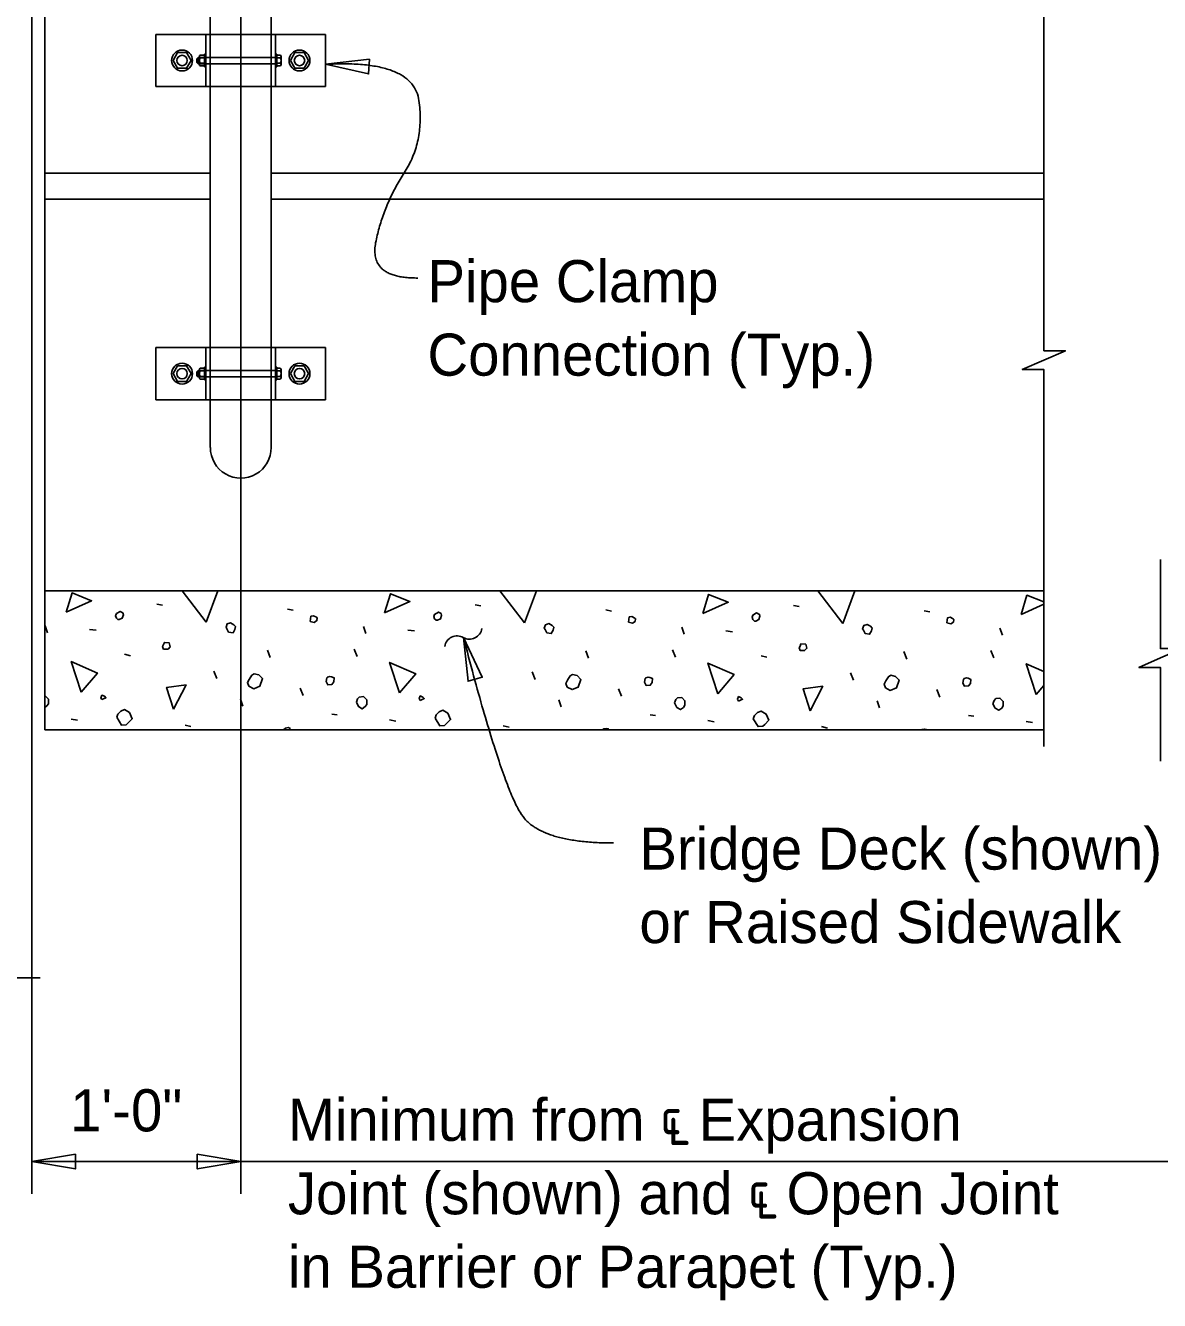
# Model space of a CAD drawing. Extents: x 0 to 72.1, y -15.2 to 30.1.
# Drawn here: x 23.6 to 29.03, y 12.88 to 18.99 of the extents above; entities that cross this region are included whole.
import ezdxf

# ---------------------------------------------------------------- set-up
doc = ezdxf.new("R2010")
doc.units = 0
for name, color, linetype in [('AdhocPoint_dp', 7, 'Continuous'), ('Border', 7, 'Continuous'), ('Patterning', 7, 'Continuous'), ('PlotBorder_dp', 7, 'Continuous'), ('SheetBorder_dp', 7, 'Continuous'), ('SheetLines_dp', 7, 'Continuous'), ('TextMisc', 7, 'Continuous')]:
    doc.layers.add(name, color=color, linetype=linetype)

msp = doc.modelspace()

# ---------------------------------------------------------------- linework, layer by layer
at = {"layer": 'AdhocPoint_dp'}
for p, q in [((23.6923, 19.2783), (23.6923, 15.6116)), ((23.6923, 18.2783), (24.4852, 18.2783)), ((24.7769, 18.2783), (28.4755, 18.2783)), ((24.7769, 18.2783), (26.018, 18.2783)), ((23.6924, 18.1533), (24.4853, 18.1533)), ((24.7769, 18.1533), (28.4756, 18.1533)), ((23.6923, 16.2783), (28.4755, 16.2783)), ((23.6923, 15.6116), (28.4755, 15.6116))]:
    msp.add_line(p, q, dxfattribs=at)
at = {"layer": 'Border'}
for p, q in [((24.4852, 18.9432), (24.4852, 18.6932)), ((24.7769, 18.9432), (24.7769, 18.6932)), ((24.7978, 18.8328), (24.4329, 18.8328)), ((24.4329, 18.8029), (24.7978, 18.8029)), ((24.4852, 17.4432), (24.4852, 17.1932)), ((24.7769, 17.4432), (24.7769, 17.1932)), ((24.7978, 17.3328), (24.4329, 17.3328)), ((24.4329, 17.3029), (24.7978, 17.3029))]:
    msp.add_line(p, q, dxfattribs=at)
at = {"layer": 'Patterning'}
for p, q in [((24.4235, 18.8113), (24.4235, 18.8234)), ((24.4292, 18.8113), (24.4292, 18.8234)), ((24.4235, 17.3113), (24.4235, 17.3234)), ((24.4292, 17.3113), (24.4292, 17.3234)), ((24.2297, 16.2147), (24.2563, 16.2094)), ((24.8555, 16.1899), (24.882, 16.1846)), ((25.7536, 16.2111), (25.7801, 16.2058)), ((26.3793, 16.1864), (26.4059, 16.1811)), ((27.2774, 16.2076), (27.3039, 16.2023)), ((27.9032, 16.1829), (27.9297, 16.1775)), ((23.7065, 16.0768), (23.6941, 16.1104)), ((23.9062, 16.0927), (23.9381, 16.0892)), ((25.2303, 16.0733), (25.2179, 16.1068)), ((25.43, 16.0892), (25.4619, 16.0856)), ((26.7541, 16.0697), (26.7417, 16.1033)), ((26.9539, 16.0856), (26.9857, 16.0821)), ((28.2779, 16.0662), (28.2655, 16.0998)), ((24.0742, 15.9743), (24.1025, 15.9672)), ((24.7724, 15.9583), (24.7583, 15.9937)), ((25.1879, 15.9636), (25.1737, 15.999)), ((26.2963, 15.9548), (26.2821, 15.9902)), ((26.7117, 15.9601), (26.6975, 15.9955)), ((27.1218, 15.9672), (27.1501, 15.9601)), ((27.8201, 15.9513), (27.8059, 15.9866)), ((28.2355, 15.9566), (28.2214, 15.9919)), ((24.5161, 15.8576), (24.502, 15.8929)), ((26.0399, 15.854), (26.0258, 15.8894)), ((27.5637, 15.8505), (27.5496, 15.8859)), ((24.6416, 15.725), (24.6293, 15.7586)), ((24.9298, 15.7763), (24.9156, 15.8116)), ((26.4536, 15.7727), (26.4394, 15.8081)), ((27.9774, 15.7692), (27.9633, 15.8046)), ((26.1654, 15.7215), (26.1531, 15.7551)), ((27.6893, 15.7179), (27.6769, 15.7515)), ((23.8196, 15.6631), (23.8497, 15.6578)), ((24.3641, 15.6348), (24.3924, 15.6278)), ((25.0677, 15.6879), (25.0924, 15.6843)), ((25.3434, 15.6596), (25.3735, 15.6543)), ((26.5915, 15.6843), (26.6162, 15.6808)), ((26.8672, 15.6561), (26.8973, 15.6508)), ((28.1153, 15.6808), (28.14, 15.6773)), ((28.3911, 15.6525), (28.4211, 15.6472)), ((25.8879, 15.6313), (25.9162, 15.6242)), ((27.4117, 15.6278), (27.44, 15.6207))]:
    msp.add_line(p, q, dxfattribs=at)
for points in [[(23.7949, 16.1758), (23.8231, 16.2677), (23.9168, 16.2306), (23.7949, 16.1758)], [(24.4648, 16.1281), (24.3507, 16.2783)], [(24.521, 16.2783), (24.4648, 16.1281)], [(25.3187, 16.1722), (25.347, 16.2642), (25.4407, 16.227), (25.3187, 16.1722)], [(25.9887, 16.1245), (25.8718, 16.2783)], [(26.0461, 16.2783), (25.9887, 16.1245)], [(26.8425, 16.1687), (26.8708, 16.2606), (26.9645, 16.2235), (26.8425, 16.1687)], [(27.5125, 16.121), (27.3929, 16.2783)], [(27.5713, 16.2783), (27.5125, 16.121)], [(28.3663, 16.1652), (28.3946, 16.2571), (28.4755, 16.225)], [(28.4755, 16.2143), (28.3663, 16.1652)], [(24.0424, 16.1404), (24.0494, 16.1404), (24.0636, 16.1475), (24.0689, 16.1634), (24.0671, 16.1722), (24.053, 16.1793), (24.0353, 16.1687), (24.0317, 16.1581), (24.0353, 16.1475), (24.0424, 16.1404)], [(24.5638, 16.0962), (24.5727, 16.0803), (24.5939, 16.0768), (24.6027, 16.0927), (24.6063, 16.1068), (24.5974, 16.1157), (24.5815, 16.1245), (24.5656, 16.1192), (24.5603, 16.1033), (24.5638, 16.0962)], [(24.9634, 16.1316), (24.9828, 16.1263), (24.9952, 16.1351), (24.9969, 16.1475), (24.9934, 16.151), (24.9793, 16.1581), (24.9669, 16.1563), (24.9651, 16.144), (24.9634, 16.1316)], [(25.5662, 16.1369), (25.5732, 16.1369), (25.5874, 16.144), (25.5927, 16.1599), (25.5909, 16.1687), (25.5768, 16.1758), (25.5591, 16.1652), (25.5556, 16.1546), (25.5591, 16.144), (25.5662, 16.1369)], [(26.4872, 16.1281), (26.5066, 16.1227), (26.519, 16.1316), (26.5208, 16.144), (26.5172, 16.1475), (26.5031, 16.1546), (26.4907, 16.1528), (26.4889, 16.1404), (26.4872, 16.1281)], [(27.09, 16.1334), (27.0971, 16.1334), (27.1112, 16.1404), (27.1165, 16.1563), (27.1147, 16.1652), (27.1006, 16.1722), (27.0829, 16.1616), (27.0794, 16.151), (27.0829, 16.1404), (27.09, 16.1334)], [(28.011, 16.1245), (28.0304, 16.1192), (28.0428, 16.1281), (28.0446, 16.1404), (28.041, 16.144), (28.0269, 16.151), (28.0145, 16.1493), (28.0128, 16.1369), (28.011, 16.1245)], [(26.0877, 16.0927), (26.0965, 16.0768), (26.1177, 16.0733), (26.1265, 16.0892), (26.1301, 16.1033), (26.1212, 16.1121), (26.1053, 16.121), (26.0894, 16.1157), (26.0841, 16.0998), (26.0877, 16.0927)], [(27.6115, 16.0892), (27.6203, 16.0733), (27.6415, 16.0697), (27.6504, 16.0856), (27.6539, 16.0998), (27.6451, 16.1086), (27.6292, 16.1174), (27.6132, 16.1121), (27.6079, 16.0962), (27.6115, 16.0892)], [(24.2616, 15.999), (24.2828, 15.999), (24.2934, 16.0096), (24.2881, 16.0291), (24.2651, 16.0308), (24.2616, 16.0202), (24.2563, 16.0114), (24.2616, 15.999), (24.258, 16.0025)], [(27.3092, 15.9919), (27.3304, 15.9919), (27.341, 16.0025), (27.3357, 16.022), (27.3127, 16.0238), (27.3092, 16.0131), (27.3039, 16.0043), (27.3092, 15.9919), (27.3057, 15.9955)], [(23.8673, 15.7922), (23.8196, 15.9389), (23.9451, 15.8841), (23.8673, 15.7922)], [(24.6699, 15.8205), (24.6929, 15.8081), (24.7229, 15.8205), (24.7353, 15.8576), (24.7176, 15.8753), (24.6947, 15.8806), (24.6841, 15.8735), (24.6717, 15.854), (24.6628, 15.8381), (24.6699, 15.8205)], [(25.3912, 15.7886), (25.3434, 15.9354), (25.4689, 15.8806), (25.3912, 15.7886)], [(26.915, 15.7851), (26.8672, 15.9318), (26.9928, 15.877), (26.915, 15.7851)], [(28.4388, 15.7816), (28.3911, 15.9283), (28.4755, 15.8914)], [(28.943, 15.9168), (28.9401, 15.9112)], [(24.3093, 15.7109), (24.2757, 15.8152), (24.3694, 15.8275), (24.3093, 15.7109)], [(25.0394, 15.8434), (25.0482, 15.8275), (25.0677, 15.8293), (25.0765, 15.8417), (25.0783, 15.8611), (25.0659, 15.8664), (25.0571, 15.8682), (25.0464, 15.8647), (25.0429, 15.8611), (25.0394, 15.8434)], [(26.1937, 15.8169), (26.2167, 15.8046), (26.2468, 15.8169), (26.2591, 15.854), (26.2415, 15.8717), (26.2185, 15.877), (26.2079, 15.87), (26.1955, 15.8505), (26.1867, 15.8346), (26.1937, 15.8169)], [(26.5632, 15.8399), (26.572, 15.824), (26.5915, 15.8258), (26.6003, 15.8381), (26.6021, 15.8576), (26.5897, 15.8629), (26.5809, 15.8647), (26.5703, 15.8611), (26.5667, 15.8576), (26.5632, 15.8399)], [(27.3569, 15.7038), (27.3233, 15.8081), (27.417, 15.8205), (27.3569, 15.7038)], [(27.7175, 15.8134), (27.7405, 15.801), (27.7706, 15.8134), (27.7829, 15.8505), (27.7653, 15.8682), (27.7423, 15.8735), (27.7317, 15.8664), (27.7193, 15.847), (27.7105, 15.8311), (27.7175, 15.8134)], [(28.087, 15.8364), (28.0958, 15.8205), (28.1153, 15.8222), (28.1241, 15.8346), (28.1259, 15.854), (28.1135, 15.8594), (28.1047, 15.8611), (28.0941, 15.8576), (28.0905, 15.854), (28.087, 15.8364)], [(28.4755, 15.825), (28.4388, 15.7816)], [(23.6923, 15.7188), (23.7029, 15.7268), (23.71, 15.7374), (23.71, 15.7586), (23.6941, 15.7745), (23.6923, 15.7743)], [(23.9663, 15.7568), (23.9858, 15.7657), (23.9787, 15.7727), (23.9663, 15.778), (23.961, 15.7657), (23.9663, 15.7568)], [(25.1843, 15.7444), (25.1949, 15.7232), (25.2126, 15.7126), (25.2268, 15.7232), (25.2338, 15.7338), (25.2338, 15.7551), (25.2179, 15.771), (25.1985, 15.7692), (25.1896, 15.7604), (25.1843, 15.7444)], [(25.4902, 15.7533), (25.5096, 15.7621), (25.5025, 15.7692), (25.4902, 15.7745), (25.4849, 15.7621), (25.4902, 15.7533)], [(26.7081, 15.7409), (26.7188, 15.7197), (26.7364, 15.7091), (26.7506, 15.7197), (26.7576, 15.7303), (26.7576, 15.7515), (26.7417, 15.7674), (26.7223, 15.7657), (26.7134, 15.7568), (26.7081, 15.7409)], [(27.014, 15.7498), (27.0334, 15.7586), (27.0263, 15.7657), (27.014, 15.771), (27.0087, 15.7586), (27.014, 15.7498)], [(28.232, 15.7374), (28.2426, 15.7162), (28.2602, 15.7056), (28.2744, 15.7162), (28.2815, 15.7268), (28.2815, 15.748), (28.2655, 15.7639), (28.2461, 15.7621), (28.2373, 15.7533), (28.232, 15.7374)], [(24.037, 15.672), (24.06, 15.6348), (24.083, 15.6366), (24.0918, 15.6455), (24.1113, 15.6649), (24.0989, 15.6949), (24.0742, 15.7091), (24.0565, 15.702), (24.0424, 15.6879), (24.037, 15.672)], [(25.5609, 15.6684), (25.5838, 15.6313), (25.6068, 15.6331), (25.6157, 15.6419), (25.6351, 15.6614), (25.6227, 15.6914), (25.598, 15.7056), (25.5803, 15.6985), (25.5662, 15.6843), (25.5609, 15.6684)], [(27.0847, 15.6649), (27.1077, 15.6278), (27.1306, 15.6295), (27.1395, 15.6384), (27.1589, 15.6578), (27.1466, 15.6879), (27.1218, 15.702), (27.1041, 15.6949), (27.09, 15.6808), (27.0847, 15.6649)], [(24.8679, 15.6116), (24.8661, 15.6207), (24.8573, 15.6225), (24.8449, 15.6207), (24.8359, 15.6116)], [(26.3911, 15.6116), (26.3899, 15.6172), (26.3811, 15.6189), (26.3687, 15.6172), (26.3632, 15.6116)], [(27.9142, 15.6116), (27.9138, 15.6136), (27.9049, 15.6154), (27.8925, 15.6136), (27.8906, 15.6116)]]:
    msp.add_lwpolyline(points, dxfattribs=at)
at = {"layer": 'PlotBorder_dp'}
msp.add_line((23.6311, 13.5439), (29.4313, 13.5439), dxfattribs=at)
for points in [[(28.4756, 19.2784), (28.4756, 17.4276), (28.5789, 17.4276), (28.4756, 17.3826), (28.3722, 17.3376), (28.4756, 17.3376), (28.4756, 15.5326)], [(29.0336, 16.4284), (29.0336, 16.0012), (29.1369, 16.0012), (29.0336, 15.9563), (28.9303, 15.9113), (29.0336, 15.9113), (29.0336, 15.4617)], [(23.6707, 14.4237), (22.9737, 14.4237), (22.9737, 14.3074), (22.8743, 14.5324), (22.8743, 14.4237), (22.2191, 14.4237)]]:
    msp.add_lwpolyline(points, dxfattribs=at)
for points in [[(25.0371, 18.7999), (25.2432, 18.7536), (25.2469, 18.8241)], [(25.6971, 16.0546), (25.7194, 15.8445), (25.7873, 15.8636)], [(23.6311, 13.544), (23.8394, 13.5087), (23.8394, 13.5792)], [(24.6311, 13.544), (24.4229, 13.5793), (24.4229, 13.5087)]]:
    msp.add_lwpolyline(points, close=True, dxfattribs=at)
for centre, start, end in [((25.6664, 16.0027), 59.84335, 171.57057), ((25.7263, 16.1058), 239.84335, 351.57057)]:
    msp.add_arc(centre, 0.0596, start, end, dxfattribs=at)
for points in [[(25.4787, 17.7763), (25.2417, 17.774), (25.3131, 18.1253), (25.5116, 18.4302), (25.4562, 18.823), (25.0371, 18.7999)], [(26.4157, 15.0702), (26.0753, 15.0702), (25.8862, 15.3257), (25.6971, 16.0545)]]:
    msp.add_open_spline(points, degree=2, dxfattribs=at)
at = {"layer": 'SheetBorder_dp'}
for p, q in [((24.6311, 13.3896), (24.6311, 27.059)), ((23.6311, 13.3896), (23.6311, 19.2851))]:
    msp.add_line(p, q, dxfattribs=at)
at = {"layer": 'TextMisc'}
for p, q in [((24.4852, 18.9432), (24.4852, 25.3183)), ((24.7769, 18.9432), (24.7769, 25.3183)), ((24.2251, 18.9432), (25.0371, 18.9432)), ((24.2251, 18.6932), (24.2251, 18.9432)), ((24.4644, 18.9432), (24.4644, 18.6932)), ((24.7977, 18.9432), (24.7977, 18.6932)), ((25.0371, 18.9432), (25.0371, 18.6932)), ((24.4207, 18.8262), (24.4263, 18.8328)), ((24.4207, 18.8085), (24.4207, 18.8262)), ((24.4263, 18.8328), (24.4329, 18.8328)), ((24.4263, 18.8029), (24.4263, 18.8328)), ((24.4329, 18.8361), (24.4329, 18.8004)), ((24.4376, 18.8312), (24.4579, 18.8312)), ((24.4378, 18.8442), (24.4579, 18.8442)), ((24.4579, 18.8485), (24.4579, 18.7879)), ((24.4579, 18.8485), (24.4644, 18.8485)), ((24.4579, 18.8442), (24.4579, 18.7922)), ((24.804, 18.8485), (24.798, 18.8485)), ((24.804, 18.8485), (24.804, 18.7879)), ((24.8187, 18.8442), (24.804, 18.8442)), ((24.8189, 18.8312), (24.804, 18.8312)), ((24.8238, 18.7988), (24.8238, 18.8377)), ((24.4207, 18.8085), (24.4263, 18.8029)), ((24.4263, 18.8029), (24.4329, 18.8029)), ((24.4376, 18.8053), (24.4579, 18.8053)), ((24.4379, 18.7922), (24.4579, 18.7922)), ((24.4579, 18.7879), (24.4644, 18.7879)), ((24.804, 18.7879), (24.798, 18.7879)), ((24.8189, 18.8052), (24.804, 18.8052)), ((24.8187, 18.7922), (24.804, 18.7922)), ((25.0371, 18.6932), (24.2251, 18.6932)), ((24.4852, 18.6932), (24.4852, 17.4432)), ((24.7769, 18.6932), (24.7769, 17.4432)), ((24.2251, 17.4432), (25.0371, 17.4432)), ((24.2251, 17.1932), (24.2251, 17.4432)), ((24.4644, 17.4432), (24.4644, 17.1932)), ((24.7977, 17.4432), (24.7977, 17.1932)), ((25.0371, 17.4432), (25.0371, 17.1932)), ((24.4378, 17.3442), (24.4579, 17.3442)), ((24.4579, 17.3485), (24.4579, 17.2879)), ((24.4579, 17.3485), (24.4644, 17.3485)), ((24.4579, 17.3442), (24.4579, 17.2922)), ((24.804, 17.3485), (24.798, 17.3485)), ((24.804, 17.3485), (24.804, 17.2879)), ((24.4207, 17.3262), (24.4263, 17.3328)), ((24.4207, 17.3085), (24.4207, 17.3262)), ((24.4207, 17.3085), (24.4263, 17.3029)), ((24.4263, 17.3328), (24.4329, 17.3328)), ((24.4263, 17.3029), (24.4263, 17.3328)), ((24.4263, 17.3029), (24.4329, 17.3029)), ((24.4329, 17.3361), (24.4329, 17.3004)), ((24.4376, 17.3312), (24.4579, 17.3312)), ((24.4376, 17.3053), (24.4579, 17.3053)), ((24.4379, 17.2922), (24.4579, 17.2922)), ((24.4579, 17.2879), (24.4644, 17.2879)), ((24.804, 17.2879), (24.798, 17.2879)), ((24.8187, 17.3442), (24.804, 17.3442)), ((24.8189, 17.3312), (24.804, 17.3312)), ((24.8189, 17.3052), (24.804, 17.3052)), ((24.8187, 17.2922), (24.804, 17.2922)), ((24.8238, 17.2988), (24.8238, 17.3377)), ((25.0371, 17.1932), (24.2251, 17.1932)), ((24.4852, 17.1932), (24.4852, 16.964)), ((24.7769, 16.964), (24.7769, 17.1932))]:
    msp.add_line(p, q, dxfattribs=at)
for points in [[(24.3284, 18.8557), (24.3718, 18.8557), (24.3934, 18.8182), (24.3718, 18.7807), (24.3284, 18.7807), (24.3067, 18.8182)], [(24.8904, 18.8557), (24.9337, 18.8557), (24.9554, 18.8182), (24.9337, 18.7807), (24.8904, 18.7807), (24.8687, 18.8182)], [(24.3284, 17.3557), (24.3718, 17.3557), (24.3934, 17.3182), (24.3718, 17.2807), (24.3284, 17.2807), (24.3067, 17.3182)], [(24.8904, 17.3557), (24.9337, 17.3557), (24.9554, 17.3182), (24.9337, 17.2807), (24.8904, 17.2807), (24.8687, 17.3182)]]:
    msp.add_lwpolyline(points, close=True, dxfattribs=at)
for centre, radius in [((24.3501, 18.8182), 0.05), ((24.3501, 18.8182), 0.025), ((24.9121, 18.8182), 0.05), ((24.9121, 18.8182), 0.025), ((24.3501, 17.3182), 0.05), ((24.9121, 17.3182), 0.05), ((24.3501, 17.3182), 0.025), ((24.9121, 17.3182), 0.025)]:
    msp.add_circle(centre, radius, dxfattribs=at)
for centre, radius, start, end in [((24.4394, 18.8377), 0.00674, 104.48908, 254.18889), ((24.4523, 18.8182), 0.0196, 138.62797, 221.37203), ((24.817, 18.8376), 0.00673, 285.7823, 75.54039), ((24.8041, 18.8182), 0.0196, 318.62797, 41.37203), ((24.4394, 18.7987), 0.00673, 105.7823, 255.54039), ((24.817, 18.7987), 0.00674, 284.48908, 74.18889), ((24.4394, 17.3377), 0.00674, 104.48908, 254.18889), ((24.4523, 17.3182), 0.0196, 138.62797, 221.37203), ((24.4394, 17.2987), 0.00673, 105.7823, 255.54039), ((24.817, 17.3376), 0.00673, 285.7823, 75.54039), ((24.817, 17.2987), 0.00674, 284.48908, 74.18889), ((24.8041, 17.3182), 0.0196, 318.62797, 41.37203)]:
    msp.add_arc(centre, radius, start, end, dxfattribs=at)
msp.add_ellipse((24.6311, 16.964), major_axis=(0, 0.1458), ratio=0.999499, start_param=1.570796, end_param=4.712389, dxfattribs=at)

# ---------------------------------------------------------------- texts
at = {"layer": 'PlotBorder_dp'}
for s, p in [('Pipe Clamp ', (25.5247, 17.6604)), ('Connection (Typ.)', (25.5247, 17.3084)), ('Bridge Deck (shown)', (26.5392, 14.9425)), ('or Raised Sidewalk', (26.5392, 14.5905)), ('Minimum from ℄ Expansion', (24.8566, 13.6435)), ('Joint (shown) and ℄ Open Joint ', (24.8566, 13.2915)), ('in Barrier or Parapet (Typ.)', (24.8566, 12.9395))]:
    msp.add_text(s, height=0.2016, dxfattribs=at).set_placement(p)
at = {"layer": 'SheetLines_dp'}
msp.add_text('1\'-0"', height=0.2016, dxfattribs=at).set_placement((23.8143, 13.6889))

doc.saveas('drawing.dxf')
